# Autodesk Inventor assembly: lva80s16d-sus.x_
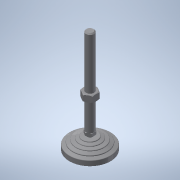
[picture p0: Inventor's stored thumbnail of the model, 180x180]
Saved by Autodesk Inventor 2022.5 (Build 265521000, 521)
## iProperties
Part Number: lva80s16d-sus.x_
Material: 一般
Document SubType Name: Assembly
Designer: ImaoCorp
Sending System: SOLIDWORKS 2017-2017317
MC: AMD64
MC_MODEL: Intel64 Family 6 Model 60 Stepping 3, GenuineIntel
OS: Windows_NT
FRU: Parasolid Version 29.0, build 201,  4-17-2017
FORMAT: text
GUISE: transmit
KEY: lva80s16d-sus
FILE: lva80s16d-sus.x_t
DATE: Mon Jul 01 18:10:14 2019
Author: ImaoCorp
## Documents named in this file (3)
- X:\14_SW2022-Inv2022\00_全2023-1023新製品(TCC)まで\l\lva80s16d-sus\LVA80S16D-SUS.iam
- X:\14_SW2022-Inv2022\00_全2023-1023新製品(TCC)まで\l\lva80s16d-sus\lva80s16d-sus_01.ipt
- X:\14_SW2022-Inv2022\00_全2023-1023新製品(TCC)まで\l\lva80s16d-sus\lva80s16d-sus_02.ipt
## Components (2 placed, 2 different names)
1. lva80s16d-sus_01
2. lva80s16d-sus_02
